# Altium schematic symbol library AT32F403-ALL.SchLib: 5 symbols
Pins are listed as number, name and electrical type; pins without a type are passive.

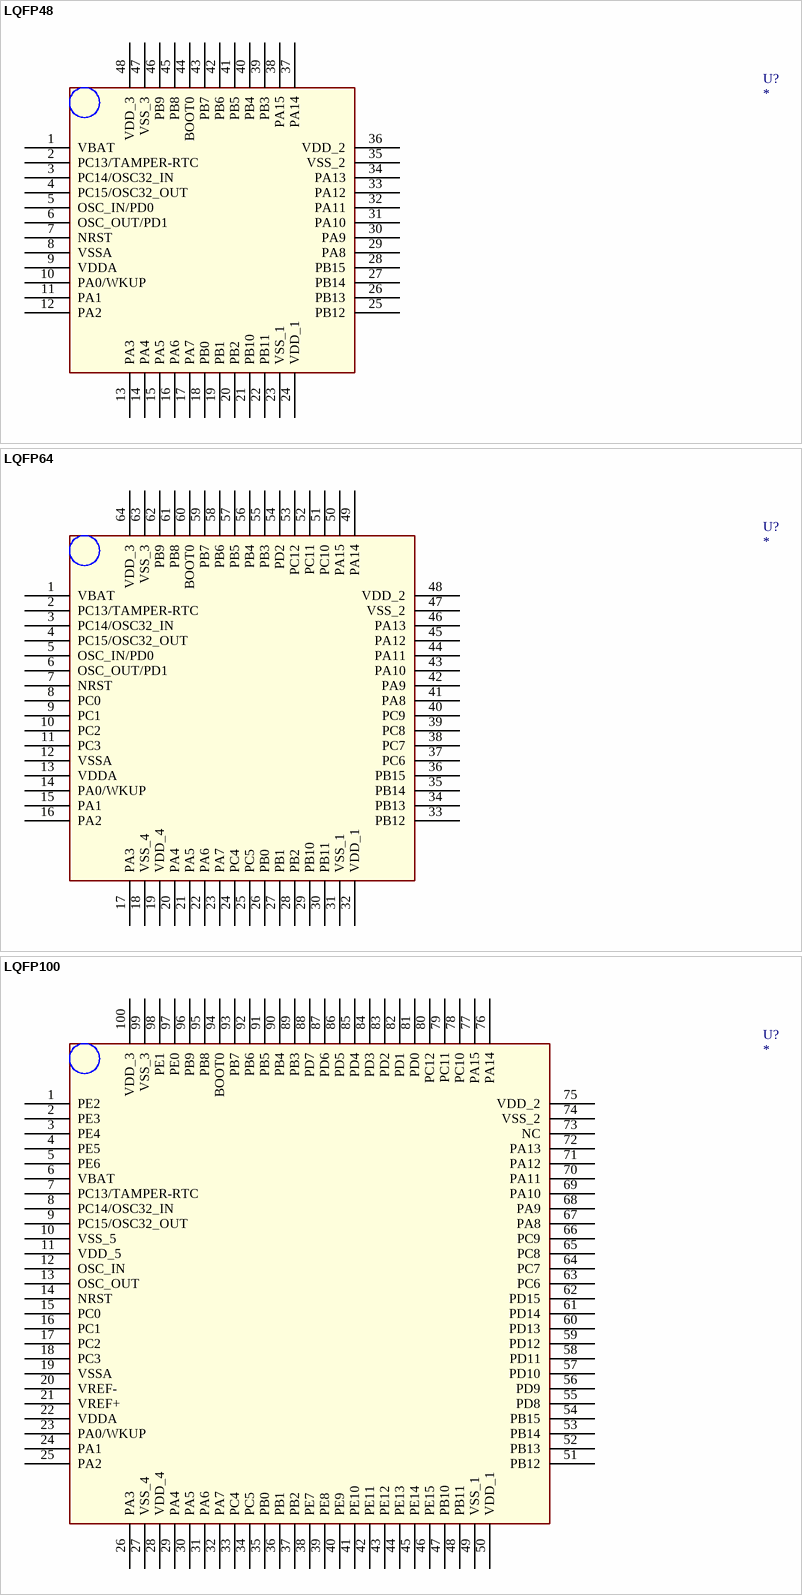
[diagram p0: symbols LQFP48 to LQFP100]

## LQFP48
designator U?
pins: 1 VBAT, 2 PC13/TAMPER-RTC, 3 PC14/OSC32_IN, 4 PC15/OSC32_OUT, 5 OSC_IN/PD0, 6 OSC_OUT/PD1, 7 NRST, 8 VSSA, 9 VDDA, 10 PA0/WKUP, 11 PA1, 12 PA2, 13 PA3, 14 PA4, 15 PA5, 16 PA6, 17 PA7, 18 PB0, 19 PB1, 20 PB2, 21 PB10, 22 PB11, 23 VSS_1, 24 VDD_1, 25 PB12, 26 PB13, 27 PB14, 28 PB15, 29 PA8, 30 PA9, 31 PA10, 32 PA11, 33 PA12, 34 PA13, 35 VSS_2, 36 VDD_2, 37 PA14, 38 PA15, 39 PB3, 40 PB4, 41 PB5, 42 PB6, 43 PB7, 44 BOOT0, 45 PB8, 46 PB9, 47 VSS_3, 48 VDD_3

## LQFP64
designator U?
pins: 1 VBAT, 2 PC13/TAMPER-RTC, 3 PC14/OSC32_IN, 4 PC15/OSC32_OUT, 5 OSC_IN/PD0, 6 OSC_OUT/PD1, 7 NRST, 8 PC0, 9 PC1, 10 PC2, 11 PC3, 12 VSSA, 13 VDDA, 14 PA0/WKUP, 15 PA1, 16 PA2, 17 PA3, 18 VSS_4, 19 VDD_4, 20 PA4, 21 PA5, 22 PA6, 23 PA7, 24 PC4, 25 PC5, 26 PB0, 27 PB1, 28 PB2, 29 PB10, 30 PB11, 31 VSS_1, 32 VDD_1, 33 PB12, 34 PB13, 35 PB14, 36 PB15, 37 PC6, 38 PC7, 39 PC8, 40 PC9, 41 PA8, 42 PA9, 43 PA10, 44 PA11, 45 PA12, 46 PA13, 47 VSS_2, 48 VDD_2, 49 PA14, 50 PA15, 51 PC10, 52 PC11, 53 PC12, 54 PD2, 55 PB3, 56 PB4, 57 PB5, 58 PB6, 59 PB7, 60 BOOT0, 61 PB8, 62 PB9, 63 VSS_3, 64 VDD_3

## LQFP100
designator U?
pins: 1 PE2, 2 PE3, 3 PE4, 4 PE5, 5 PE6, 6 VBAT, 7 PC13/TAMPER-RTC, 8 PC14/OSC32_IN, 9 PC15/OSC32_OUT, 10 VSS_5, 11 VDD_5, 12 OSC_IN, 13 OSC_OUT, 14 NRST, 15 PC0, 16 PC1, 17 PC2, 18 PC3, 19 VSSA, 20 VREF-, 21 VREF+, 22 VDDA, 23 PA0/WKUP, 24 PA1, 25 PA2, 26 PA3, 27 VSS_4, 28 VDD_4, 29 PA4, 30 PA5, 31 PA6, 32 PA7, 33 PC4, 34 PC5, 35 PB0, 36 PB1, 37 PB2, 38 PE7, 39 PE8, 40 PE9, 41 PE10, 42 PE11, 43 PE12, 44 PE13, 45 PE14, 46 PE15, 47 PB10, 48 PB11, 49 VSS_1, 50 VDD_1, 51 PB12, 52 PB13, 53 PB14, 54 PB15, 55 PD8, 56 PD9, 57 PD10, 58 PD11, 59 PD12, 60 PD13, 61 PD14, 62 PD15, 63 PC6, 64 PC7, 65 PC8, 66 PC9, 67 PA8, 68 PA9, 69 PA10, 70 PA11, 71 PA12, 72 PA13, 73 NC, 74 VSS_2, 75 VDD_2, 76 PA14, 77 PA15, 78 PC10, 79 PC11, 80 PC12, 81 PD0, 82 PD1, 83 PD2, 84 PD3, 85 PD4, 86 PD5, 87 PD6, 88 PD7, 89 PB3, 90 PB4, 91 PB5, 92 PB6, 93 PB7, 94 BOOT0, 95 PB8, 96 PB9, 97 PE0, 98 PE1, 99 VSS_3, 100 VDD_3

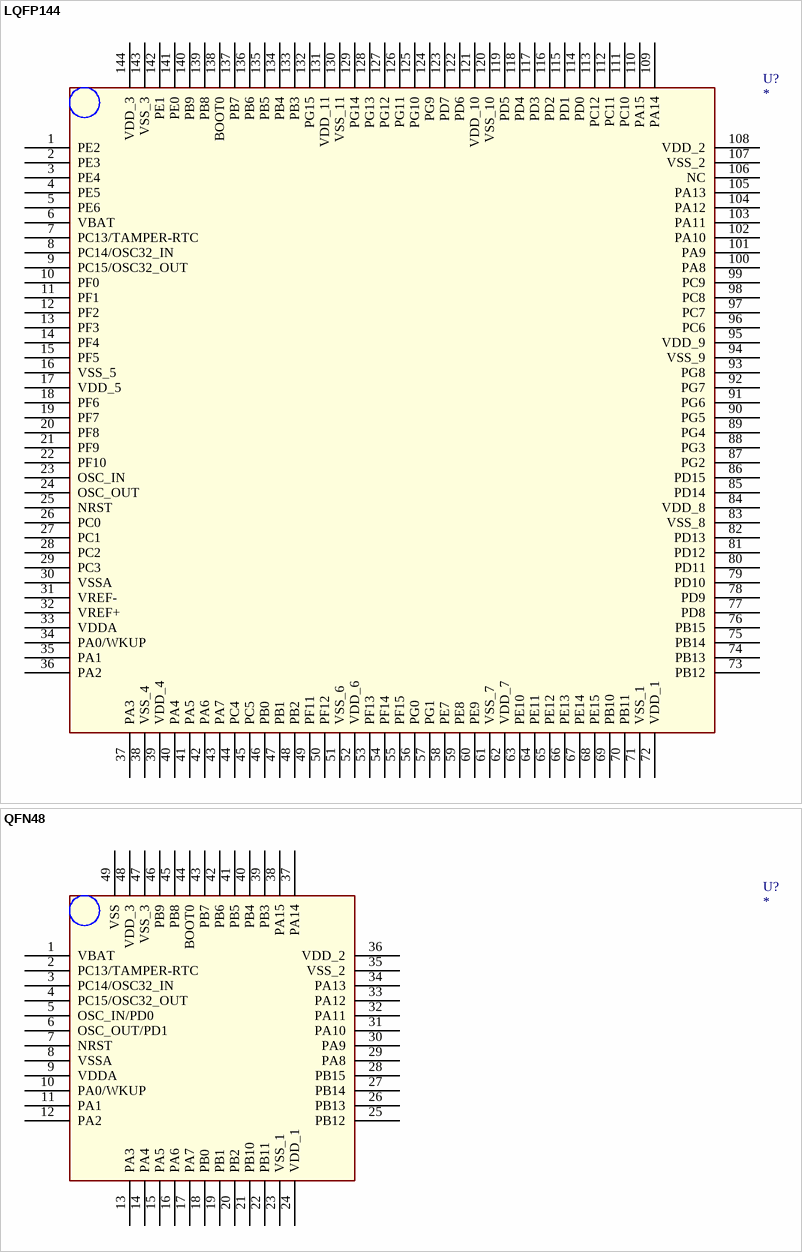
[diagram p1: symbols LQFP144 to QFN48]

## LQFP144
designator U?
pins: 1 PE2, 2 PE3, 3 PE4, 4 PE5, 5 PE6, 6 VBAT, 7 PC13/TAMPER-RTC, 8 PC14/OSC32_IN, 9 PC15/OSC32_OUT, 10 PF0, 11 PF1, 12 PF2, 13 PF3, 14 PF4, 15 PF5, 16 VSS_5, 17 VDD_5, 18 PF6, 19 PF7, 20 PF8, 21 PF9, 22 PF10, 23 OSC_IN, 24 OSC_OUT, 25 NRST, 26 PC0, 27 PC1, 28 PC2, 29 PC3, 30 VSSA, 31 VREF-, 32 VREF+, 33 VDDA, 34 PA0/WKUP, 35 PA1, 36 PA2, 37 PA3, 38 VSS_4, 39 VDD_4, 40 PA4, 41 PA5, 42 PA6, 43 PA7, 44 PC4, 45 PC5, 46 PB0, 47 PB1, 48 PB2, 49 PF11, 50 PF12, 51 VSS_6, 52 VDD_6, 53 PF13, 54 PF14, 55 PF15, 56 PG0, 57 PG1, 58 PE7, 59 PE8, 60 PE9, 61 VSS_7, 62 VDD_7, 63 PE10, 64 PE11, 65 PE12, 66 PE13, 67 PE14, 68 PE15, 69 PB10, 70 PB11, 71 VSS_1, 72 VDD_1, 73 PB12, 74 PB13, 75 PB14, 76 PB15, 77 PD8, 78 PD9, 79 PD10, 80 PD11, 81 PD12, 82 PD13, 83 VSS_8, 84 VDD_8, 85 PD14, 86 PD15, 87 PG2, 88 PG3, 89 PG4, 90 PG5, 91 PG6, 92 PG7, 93 PG8, 94 VSS_9, 95 VDD_9, 96 PC6, 97 PC7, 98 PC8, 99 PC9, 100 PA8, 101 PA9, 102 PA10, 103 PA11, 104 PA12, 105 PA13, 106 NC, 107 VSS_2, 108 VDD_2, 109 PA14, 110 PA15, 111 PC10, 112 PC11, 113 PC12, 114 PD0, 115 PD1, 116 PD2, 117 PD3, 118 PD4, 119 PD5, 120 VSS_10, 121 VDD_10, 122 PD6, 123 PD7, 124 PG9, 125 PG10, 126 PG11, 127 PG12, 128 PG13, 129 PG14, 130 VSS_11, 131 VDD_11, 132 PG15, 133 PB3, 134 PB4, 135 PB5, 136 PB6, 137 PB7, 138 BOOT0, 139 PB8, 140 PB9, 141 PE0, 142 PE1, 143 VSS_3, 144 VDD_3

## QFN48
designator U?
pins: 1 VBAT, 2 PC13/TAMPER-RTC, 3 PC14/OSC32_IN, 4 PC15/OSC32_OUT, 5 OSC_IN/PD0, 6 OSC_OUT/PD1, 7 NRST, 8 VSSA, 9 VDDA, 10 PA0/WKUP, 11 PA1, 12 PA2, 13 PA3, 14 PA4, 15 PA5, 16 PA6, 17 PA7, 18 PB0, 19 PB1, 20 PB2, 21 PB10, 22 PB11, 23 VSS_1, 24 VDD_1, 25 PB12, 26 PB13, 27 PB14, 28 PB15, 29 PA8, 30 PA9, 31 PA10, 32 PA11, 33 PA12, 34 PA13, 35 VSS_2, 36 VDD_2, 37 PA14, 38 PA15, 39 PB3, 40 PB4, 41 PB5, 42 PB6, 43 PB7, 44 BOOT0, 45 PB8, 46 PB9, 47 VSS_3, 48 VDD_3, 49 VSS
